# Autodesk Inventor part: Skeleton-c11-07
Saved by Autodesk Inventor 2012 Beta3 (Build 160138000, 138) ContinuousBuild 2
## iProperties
Created: 2011-01
Part Number: Skeleton-c11-07
Material: Default
Document SubType Name: Modeling
Designer: Beta-8540w
Density: 1 g/cm^3
_SkeletonDoc: Frame Skeleton File
_Version: 15.0.0
Author: Beta-8540w
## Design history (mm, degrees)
sketch "Reference Skeleton"
  geometry: L1 through (404.523, 1164.395) direction (1, 0); L2 through (325.691, 1070.446) direction (1, 0); 34 other entities
  constraints: 10 horizontal
